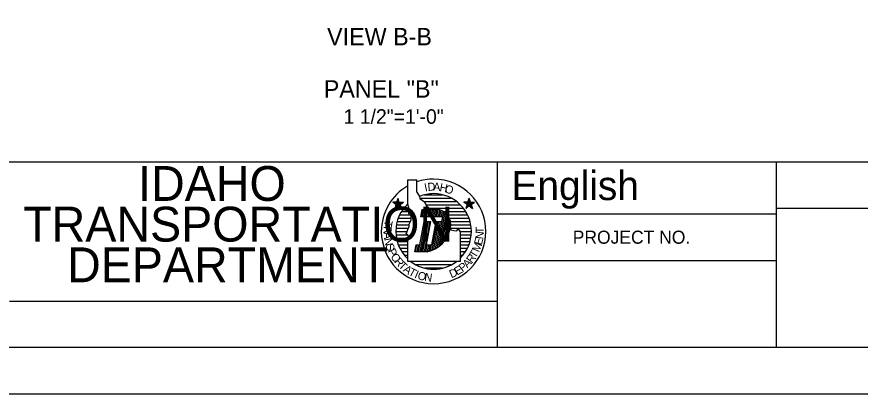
# Model space of a CAD drawing. Extents: x 0 to 22.7, y 0 to 15.7.
# Drawn here: x 9.39 to 15.43, y 0 to 2.7 of the extents above; entities that cross this region are included whole.
import ezdxf

# ---------------------------------------------------------------- set-up
doc = ezdxf.new("R2010")
doc.units = 0
for name, color, linetype in [('BORDER_ANNO_Cutsheet', 7, 'Continuous'), ('BRDG_ANNO_Anno-Sheet', 7, 'Continuous'), ('BRDG_ANNO_General-Notes', 7, 'Continuous')]:
    doc.layers.add(name, color=color, linetype=linetype)

msp = doc.modelspace()

# ---------------------------------------------------------------- linework, layer by layer
at = {"layer": 'BORDER_ANNO_Cutsheet'}
msp.add_lwpolyline([(0, 14.6667), (22.6667, 14.6667), (22.6667, 0), (0, 0)], close=True, dxfattribs=at)
at = {"layer": 'BRDG_ANNO_Anno-Sheet'}
for p, q in [((1, 1.6667), (12.8333, 1.6667)), ((12.8333, 0.3333), (12.8333, 1.6667)), ((12.8333, 1.6667), (22.3333, 1.6667)), ((14.8333, 0.3333), (14.8333, 1.6667)), ((12.1896, 1.3617), (12.1896, 1.5354)), ((12.1896, 1.5354), (12.2554, 1.5354)), ((12.2554, 1.4487), (12.2554, 1.5354)), ((12.1104, 1.3771), (12.1196, 1.4046)), ((12.1196, 1.3492), (12.1196, 1.4046)), ((12.1288, 1.3771), (12.1196, 1.4046)), ((12.2554, 1.4487), (12.2729, 1.4175)), ((12.2729, 1.4175), (12.2762, 1.4033)), ((12.2762, 1.4033), (12.3108, 1.3792)), ((12.2779, 1.4054), (12.5004, 1.4054)), ((12.31, 1.4296), (12.4387, 1.4296)), ((12.6212, 1.3771), (12.6304, 1.4046)), ((12.6304, 1.3492), (12.6304, 1.4046)), ((12.6396, 1.3771), (12.6304, 1.4046)), ((12.1342, 1.36), (12.0817, 1.3771)), ((12.1104, 1.3771), (12.0817, 1.3771)), ((12.105, 1.36), (12.0817, 1.3771)), ((12.1288, 1.3771), (12.0958, 1.3321)), ((12.105, 1.36), (12.0958, 1.3321)), ((12.1196, 1.3492), (12.0958, 1.3321)), ((12.105, 1.36), (12.1579, 1.3771)), ((12.1104, 1.3771), (12.1433, 1.3321)), ((12.1196, 1.3492), (12.1433, 1.3321)), ((12.1288, 1.3771), (12.1579, 1.3771)), ((12.1342, 1.36), (12.1579, 1.3771)), ((12.1342, 1.36), (12.1433, 1.3321)), ((12.1612, 1.3337), (12.1958, 1.3337)), ((12.1829, 1.3575), (12.1908, 1.3575)), ((12.1962, 1.3375), (12.1896, 1.3617)), ((12.1962, 1.3167), (12.1962, 1.3375)), ((12.31, 1.3817), (12.5379, 1.3817)), ((12.3108, 1.3792), (12.3217, 1.3513)), ((12.3192, 1.3575), (12.5671, 1.3575)), ((12.3217, 1.3513), (12.3562, 1.3237)), ((12.3438, 1.3337), (12.5883, 1.3337)), ((12.645, 1.36), (12.5921, 1.3771)), ((12.6158, 1.36), (12.5921, 1.3771)), ((12.6212, 1.3771), (12.5921, 1.3771)), ((12.6396, 1.3771), (12.6067, 1.3321)), ((12.6158, 1.36), (12.6067, 1.3321)), ((12.6304, 1.3492), (12.6067, 1.3321)), ((12.6158, 1.36), (12.6683, 1.3771)), ((12.6212, 1.3771), (12.6542, 1.3321)), ((12.6304, 1.3492), (12.6542, 1.3321)), ((12.6396, 1.3771), (12.6683, 1.3771)), ((12.645, 1.36), (12.6683, 1.3771)), ((12.645, 1.36), (12.6542, 1.3321)), ((14.8333, 1.3333), (20.1667, 1.3333)), ((12.1312, 1.2854), (12.1988, 1.2854)), ((12.1446, 1.3096), (12.195, 1.3096)), ((12.1962, 1.2992), (12.1962, 1.3167)), ((12.2, 1.2854), (12.1962, 1.2992)), ((12.2137, 1.2783), (12.2, 1.2854)), ((12.2137, 1.2608), (12.2137, 1.2783)), ((12.2833, 1.2712), (12.2937, 1.3237)), ((12.4408, 1.2712), (12.2833, 1.2712)), ((12.2929, 1.2712), (12.3025, 1.3237)), ((12.2937, 1.3237), (12.4083, 1.3237)), ((12.3033, 1.2712), (12.3133, 1.3237)), ((12.3142, 1.2712), (12.3238, 1.3237)), ((12.3246, 1.2712), (12.3346, 1.3237)), ((12.335, 1.2712), (12.345, 1.3237)), ((12.3458, 1.2712), (12.3554, 1.3237)), ((12.3562, 1.2712), (12.3662, 1.3237)), ((12.3671, 1.2712), (12.3767, 1.3237)), ((12.3775, 1.2712), (12.3875, 1.3237)), ((12.3883, 1.2712), (12.3979, 1.3237)), ((12.3987, 1.2712), (12.4087, 1.3237)), ((12.3996, 1.0496), (12.4479, 1.3079)), ((12.4092, 1.2712), (12.4187, 1.3208)), ((12.4117, 1.0571), (12.4575, 1.3013)), ((12.42, 1.2712), (12.4287, 1.3179)), ((12.4242, 1.0671), (12.4662, 1.2925)), ((12.4304, 1.2712), (12.4383, 1.3133)), ((12.4346, 1.2367), (12.4408, 1.2712)), ((12.4371, 1.0792), (12.475, 1.2829)), ((12.4458, 1.3096), (12.605, 1.3096)), ((12.4504, 1.0933), (12.4833, 1.2708)), ((12.4733, 1.2854), (12.6183, 1.2854)), ((12.8333, 1.2917), (14.8333, 1.2917)), ((12.1083, 1.2137), (12.1988, 1.2137)), ((12.1137, 1.2375), (12.2075, 1.2375)), ((12.1208, 1.2617), (12.2125, 1.2617)), ((12.2, 1.2192), (12.2067, 1.2333)), ((12.2, 1.2021), (12.2, 1.2192)), ((12.2067, 1.2333), (12.2137, 1.2504)), ((12.2137, 1.2504), (12.2137, 1.2608)), ((12.2762, 1.07), (12.3075, 1.2367)), ((12.2775, 1.0212), (12.3179, 1.2367)), ((12.2883, 1.0212), (12.3287, 1.2367)), ((12.2988, 1.0212), (12.3392, 1.2367)), ((12.3075, 1.2367), (12.3533, 1.2367)), ((12.3096, 1.0212), (12.35, 1.2367)), ((12.3533, 1.2367), (12.3221, 1.07)), ((12.3625, 1.07), (12.3937, 1.2367)), ((12.3646, 1.0317), (12.4029, 1.2367)), ((12.3758, 1.0367), (12.4133, 1.2367)), ((12.3875, 1.0421), (12.4242, 1.2367)), ((12.3937, 1.2367), (12.4346, 1.2367)), ((12.4646, 1.1125), (12.4912, 1.2546)), ((12.4812, 1.145), (12.4971, 1.23)), ((12.4883, 1.2617), (12.6288, 1.2617)), ((12.4962, 1.2375), (12.6363, 1.2375)), ((12.4983, 1.2137), (12.6417, 1.2137)), ((12.1042, 1.1654), (12.185, 1.1654)), ((12.105, 1.1896), (12.1937, 1.1896)), ((12.1792, 1.15), (12.1858, 1.1671)), ((12.1896, 1.1396), (12.1792, 1.15)), ((12.1858, 1.1671), (12.1896, 1.1812)), ((12.1896, 1.1812), (12.2, 1.2021)), ((12.4938, 1.185), (12.4987, 1.1775)), ((12.495, 1.1896), (12.645, 1.1896)), ((12.4987, 1.1775), (12.5196, 1.1742)), ((12.5196, 1.1742), (12.5404, 1.1708)), ((12.5404, 1.1708), (12.5508, 1.1846)), ((12.5508, 1.1846), (12.5646, 1.1638)), ((12.5633, 1.1654), (12.6458, 1.1654)), ((12.5646, 1.1638), (12.5646, 0.9517)), ((12.1054, 1.1417), (12.1875, 1.1417)), ((12.1087, 1.1175), (12.1988, 1.1175)), ((12.1142, 1.0938), (12.1892, 1.0938)), ((12.1962, 1.1292), (12.1896, 1.1396)), ((12.1896, 1.1013), (12.2, 1.1117)), ((12.1896, 0.9517), (12.1896, 1.1013)), ((12.2, 1.1221), (12.1962, 1.1292)), ((12.2, 1.1117), (12.2, 1.1221)), ((12.5646, 1.1175), (12.6412, 1.1175)), ((12.5646, 1.0938), (12.6358, 1.0938)), ((12.565, 1.1417), (12.6446, 1.1417)), ((12.1225, 1.0696), (12.1883, 1.0696)), ((12.1329, 1.0454), (12.1883, 1.0454)), ((12.2396, 1.0212), (12.2487, 1.07)), ((12.2458, 1.0212), (12.255, 1.07)), ((12.2487, 1.07), (12.2762, 1.07)), ((12.2567, 1.0212), (12.2658, 1.07)), ((12.2671, 1.0212), (12.2762, 1.07)), ((12.32, 1.0212), (12.3292, 1.07)), ((12.3221, 1.07), (12.3625, 1.07)), ((12.3308, 1.0217), (12.34, 1.07)), ((12.3421, 1.0246), (12.3504, 1.07)), ((12.3533, 1.0279), (12.3608, 1.07)), ((12.5646, 1.0696), (12.6275, 1.0696)), ((12.5646, 1.0454), (12.6167, 1.0454)), ((12.1467, 1.0217), (12.1887, 1.0217)), ((12.1638, 0.9975), (12.1883, 0.9975)), ((12.185, 0.9738), (12.1892, 0.9738)), ((12.3283, 1.0212), (12.2396, 1.0212)), ((12.5646, 1.0217), (12.6033, 1.0217)), ((12.5646, 0.9975), (12.5867, 0.9975)), ((12.5646, 0.9517), (12.1896, 0.9517)), ((12.5004, 0.9275), (12.2479, 0.9275)), ((12.8333, 0.9583), (14.8333, 0.9583)), ((12.4392, 0.9037), (12.3117, 0.9037)), ((9.3333, 0.6667), (12.8333, 0.6667))]:
    msp.add_line(p, q, dxfattribs=at)
msp.add_lwpolyline([(1, 14.3333), (22.3333, 14.3333), (22.3333, 0.3333), (1, 0.3333)], close=True, dxfattribs=at)
for centre, radius, start, end in [((12.375, 1.1667), 0.375, 90, 108.596), ((12.375, 1.1667), 0.375, 0, 90), ((12.375, 1.1667), 0.375, 119.63312, 180), ((12.375, 1.1667), 0.2708, 90, 112.14518), ((12.375, 1.1667), 0.2708, 0, 90), ((12.375, 1.1667), 0.2708, 133.19257, 180), ((12.3888, 1.2161), 0.1094, 343.49805, 79.73615), ((12.375, 1.1667), 0.375, 180, 270), ((12.375, 1.1667), 0.2708, 180.26444, 226.79463), ((12.2899, 1.2255), 0.2078, 280.64795, 348.77185), ((12.375, 1.1667), 0.375, 270, 0), ((12.375, 1.1667), 0.2708, 314.427, 0), ((12.375, 1.1667), 0.2708, 232.5658, 270), ((12.375, 1.1667), 0.2708, 270, 307.45359)]:
    msp.add_arc(centre, radius, start, end, dxfattribs=at)

# ---------------------------------------------------------------- texts
for s, height, p in [('IDAHO', 0.25, (10.2558, 1.3854)), ('English', 0.20833, (12.9337, 1.3912)), ('TRANSPORTATION', 0.25, (9.4313, 1.0938)), ('PROJECT NO.', 0.09375, (13.3728, 1.0783)), ('DEPARTMENT', 0.25, (9.7462, 0.8021))]:
    msp.add_text(s, height=height, dxfattribs=at).set_placement(p)
for s, rotation, p in [('D', 5.21184, (12.3342, 1.4563)), ('A', 357.8718, (12.3712, 1.4587)), ('I', 11.95188, (12.3146, 1.4521)), ('H', 349.63177, (12.4146, 1.4558)), ('O', 342.19173, (12.4496, 1.4487)), ('T', 259.42648, (12.0254, 1.2504)), ('R', 266.0275, (12.0175, 1.205)), ('A', 273.76404, (12.0154, 1.1604)), ('N', 83.19321, (12.73, 1.1087)), ('T', 90.49256, (12.7346, 1.1529)), ('N', 280.37584, (12.0192, 1.1142)), ('M', 67.71394, (12.7004, 1.0137)), ('E', 75.61046, (12.7196, 1.0646)), ('S', 287.92792, (12.0287, 1.0692)), ('P', 295.49755, (12.0437, 1.0271)), ('T', 59.03624, (12.6758, 0.97)), ('O', 302.64464, (12.0637, 0.9867)), ('R', 309.90789, (12.0892, 0.9483)), ('R', 52.33438, (12.6492, 0.9342)), ('T', 317.1211, (12.1183, 0.9142)), ('A', 324.63754, (12.1521, 0.8837)), ('T', 331.75026, (12.1896, 0.8579)), ('E', 30.54757, (12.5437, 0.8492)), ('P', 37.66562, (12.5821, 0.8729)), ('A', 45, (12.6171, 0.9004)), ('I', 337.0213, (12.2329, 0.8358)), ('O', 343.32869, (12.255, 0.8271)), ('N', 351.65981, (12.3058, 0.8133)), ('D', 22.98872, (12.5021, 0.8304))]:
    msp.add_text(s, height=0.0579, rotation=rotation, dxfattribs=at).set_placement(p)
at = {"layer": 'BRDG_ANNO_General-Notes'}
for s, height, p in [('VIEW B-B', 0.125, (11.6109, 2.5007)), ('PANEL "B"', 0.125, (11.5872, 2.1257)), ('1 1/2"=1\'-0"', 0.104167, (11.7292, 1.9382))]:
    msp.add_text(s, height=height, dxfattribs=at).set_placement(p)

doc.saveas('drawing.dxf')
